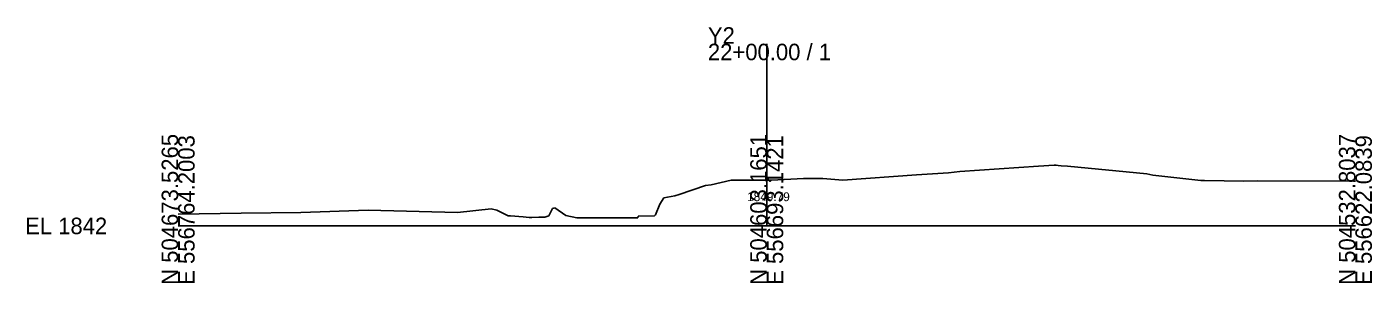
# Model space of a CAD drawing. Extents: x -26 to 1503, y -10 to 3574.
# Drawn here: x -25.7 to 202.8, y 1990.3 to 2033.8 of the extents above; entities that cross this region are included whole.
import ezdxf

# ---------------------------------------------------------------- set-up
doc = ezdxf.new("R2010")
doc.units = 0
for name, color, linetype in [('Default', 7, 'Continuous'), ('Exist Cross Section Cell', 7, 'Continuous'), ('Exist XS Center Line Elevation Label', 7, 'Continuous'), ('Exist XS Ground Line', 7, 'Continuous')]:
    doc.layers.add(name, color=color, linetype=linetype)

msp = doc.modelspace()

# ---------------------------------------------------------------- linework, layer by layer
at = {"layer": 'Exist Cross Section Cell'}
for p, q in [((100, 2000), (100, 2030.91)), ((0, 2000), (100, 2000)), ((100, 2000), (200, 2000))]:
    msp.add_line(p, q, dxfattribs=at)
at = {"layer": 'Exist XS Ground Line'}
for p, q in [((125.43, 2008.67), (130.86, 2009)), ((130.86, 2009), (132.81, 2009.21)), ((132.81, 2009.21), (146.14, 2010.16)), ((146.14, 2010.16), (148.81, 2010.3)), ((148.81, 2010.3), (149.16, 2010.28)), ((149.16, 2010.28), (149.52, 2010.26)), ((149.52, 2010.26), (150.01, 2010.22)), ((150.01, 2010.22), (151.12, 2010.13)), ((151.12, 2010.13), (164.56, 2008.81)), ((164.56, 2008.81), (165.61, 2008.59)), ((85.14, 2005.35), (89.62, 2006.88)), ((89.62, 2006.88), (90.57, 2006.99)), ((90.57, 2006.99), (93.95, 2007.76)), ((93.95, 2007.76), (100, 2007.79)), ((100, 2007.79), (100.78, 2007.79)), ((100.78, 2007.79), (106.22, 2008.06)), ((106.22, 2008.06), (109.53, 2008.05)), ((109.53, 2008.05), (112.92, 2007.75)), ((112.92, 2007.75), (125.43, 2008.67)), ((165.61, 2008.59), (173.74, 2007.73)), ((173.74, 2007.73), (174.36, 2007.73)), ((174.36, 2007.73), (181.04, 2007.62)), ((181.04, 2007.62), (183.41, 2007.63)), ((183.41, 2007.63), (199.66, 2007.62)), ((199.66, 2007.62), (200, 2007.62)), ((81.85, 2003.67), (82.52, 2004.79)), ((82.52, 2004.79), (84.36, 2005.12)), ((84.36, 2005.12), (85.14, 2005.35)), ((0, 2001.97), (10.7, 2002.19)), ((10.7, 2002.19), (20.85, 2002.28)), ((20.85, 2002.28), (32.27, 2002.65)), ((32.27, 2002.65), (47.48, 2002.3)), ((47.48, 2002.3), (53.19, 2002.89)), ((53.19, 2002.89), (54.15, 2002.67)), ((54.15, 2002.67), (56.05, 2001.73)), ((62.99, 2001.69), (63.6, 2002.97)), ((63.6, 2002.97), (63.99, 2003.06)), ((63.99, 2003.06), (65.84, 2001.78)), ((81.08, 2001.86), (81.85, 2003.67)), ((56.05, 2001.73), (56.47, 2001.72)), ((56.47, 2001.72), (58.6, 2001.57)), ((58.6, 2001.57), (59.65, 2001.44)), ((59.65, 2001.44), (60.09, 2001.45)), ((60.09, 2001.45), (61.28, 2001.46)), ((61.28, 2001.46), (62.27, 2001.51)), ((62.27, 2001.51), (62.99, 2001.69)), ((65.84, 2001.78), (65.89, 2001.79)), ((65.89, 2001.79), (67.75, 2001.4)), ((67.75, 2001.4), (78.11, 2001.36)), ((78.11, 2001.36), (78.15, 2001.63)), ((78.15, 2001.63), (80.92, 2001.73)), ((80.92, 2001.73), (81.08, 2001.86))]:
    msp.add_line(p, q, dxfattribs=at)

# ---------------------------------------------------------------- texts
at = {"layer": 'Default'}
msp.add_text('-', height=0.0001, dxfattribs=at).set_placement((0, 2000))
at = {"layer": 'Exist Cross Section Cell'}
for s, p in [('Y2', (90, 2030.91)), ('22+00.00 / 1', (90, 2028.11)), ('EL 1842', (-26, 1998.6))]:
    msp.add_text(s, height=2.8, dxfattribs=at).set_placement(p)
for s, p in [('N 504673.5265', (0, 1990)), ('E 556764.2003', (2.8, 1990)), ('N 504603.1651', (100, 1990)), ('E 556693.1421', (102.8, 1990)), ('N 504532.8037', (200, 1990)), ('E 556622.0839', (202.8, 1990))]:
    msp.add_text(s, height=2.8, rotation=90, dxfattribs=at).set_placement(p)
at = {"layer": 'Exist XS Center Line Elevation Label'}
msp.add_text('1849.79', height=1.5, dxfattribs=at).set_placement((96.66, 2004.2))

doc.saveas('drawing.dxf')
